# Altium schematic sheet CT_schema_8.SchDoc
size 277 x 170 mm
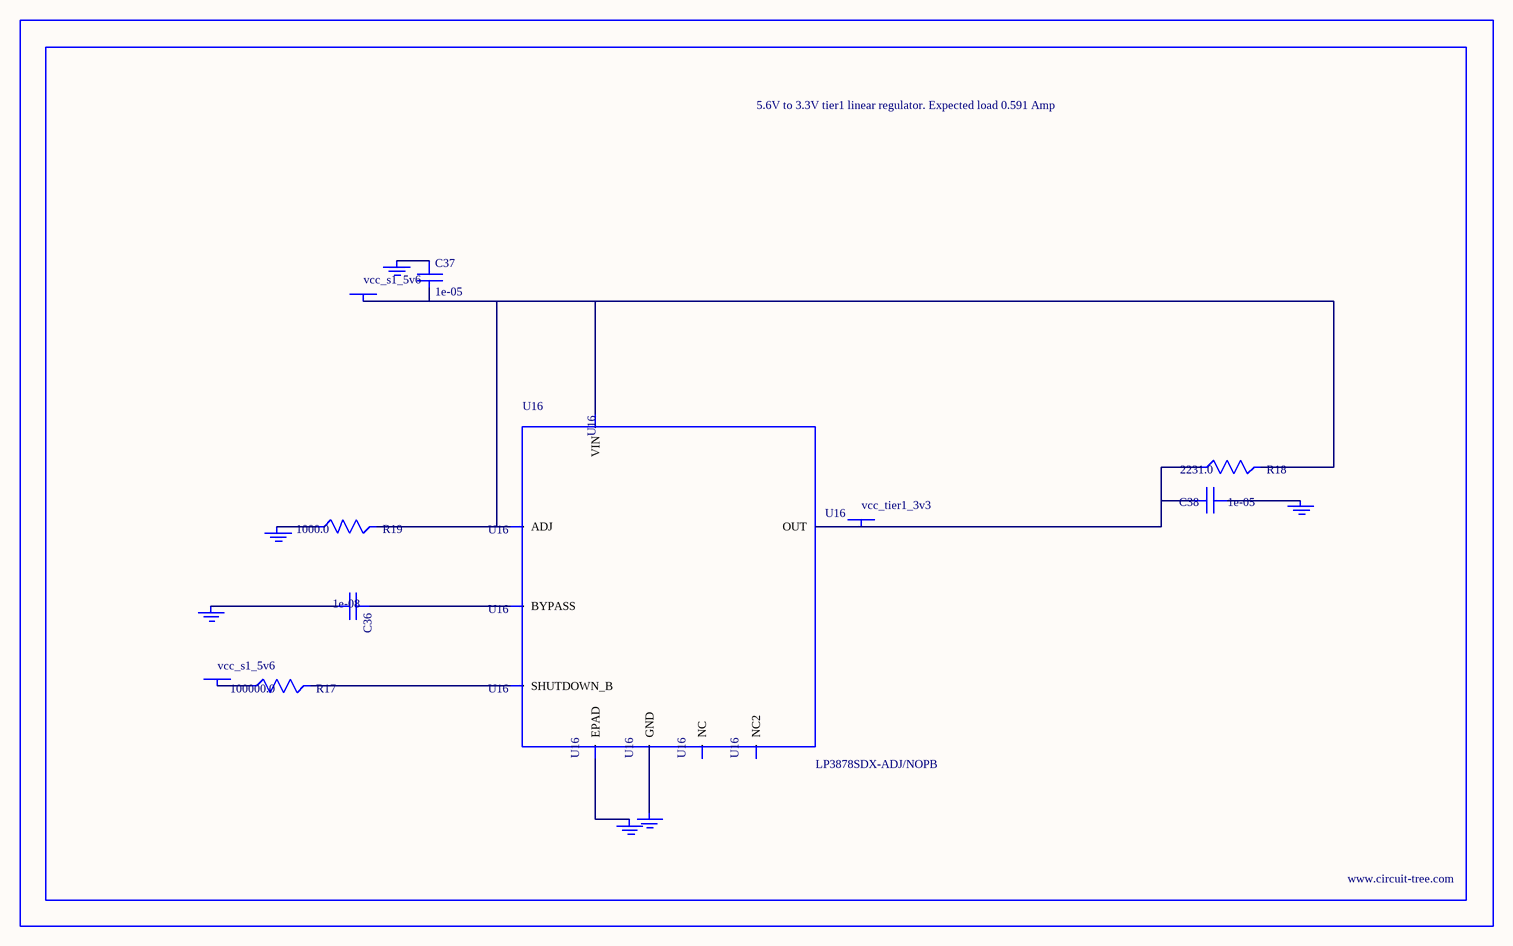
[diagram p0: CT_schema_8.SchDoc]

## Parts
BORDER7  (no value)
C36  1e-08  [C0402]
C37  1e-05  [C1206]
C38  1e-05  [C1210]
GND_INSTANCE_7_0  (no value)
GND_INSTANCE_7_1  (no value)
GND_INSTANCE_7_2  (no value)
GND_INSTANCE_7_3  (no value)
GND_INSTANCE_7_4  (no value)
GND_INSTANCE_7_5  (no value)
POWER_INSTANCE_7_0  vcc_s1_5v6
POWER_INSTANCE_7_1  vcc_s1_5v6
POWER_INSTANCE_7_2  vcc_tier1_3v3
R17  100000.0  [R0603]
R18  2231.0  [R0603]
R19  1000.0  [R0603]
U16  LP3878SDX-ADJ/NOPB  [WSON-8]

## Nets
NetC36_1: C36.1 U16.1(BYPASS)
NetC36_2: C36.2 GND_INSTANCE_7_0.0(GND)
NetC37_1: C37.1 GND_INSTANCE_7_1.0(GND)
NetC37_2: C37.2 POWER_INSTANCE_7_0.0(PWR) R18.2 R19.2 U16.4(VIN) U16.6(ADJ)
NetC38_1: C38.1 GND_INSTANCE_7_2.0(GND)
NetC38_2: C38.2 POWER_INSTANCE_7_2.0(PWR) R18.1 U16.5(OUT)
NetGND_INSTANCE_7_3_0: GND_INSTANCE_7_3.0(GND) R19.1
NetGND_INSTANCE_7_4_0: GND_INSTANCE_7_4.0(GND) U16.PAD(EPAD)
NetGND_INSTANCE_7_5_0: GND_INSTANCE_7_5.0(GND) U16.3(GND)
NetPOWER_INSTANCE_7_1_0: POWER_INSTANCE_7_1.0(PWR) R17.1
NetR17_2: R17.2 U16.8(SHUTDOWN_B)

Not connected (* = marked no-connect by the designer): U16 2(NC) 7(NC2)

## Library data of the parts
BORDER7 = BORDER_PAGE7
C36 = C0402C103K3RAC
C37 = C1206C106K3RACTU
C38 = GRM32DR61E106MA12L
GND_INSTANCE_7_0-GND_INSTANCE_7_5 = GND
POWER_INSTANCE_7_0-POWER_INSTANCE_7_2 = PWR
R17 = RC0603JR-07100KL
R18 = R18
R19 = RC0603JR-071KL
